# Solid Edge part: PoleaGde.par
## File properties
Author: there
Template: iso metric part.par
Last saved by: there
Revision: 3
Application: Solid Edge
Precisión: 0.990
Username: there
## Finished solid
Body 1: solid body, 8 faces, 8 edges, 0 vertices.
  Faces by surface: cylinder 4, plane 4
  Edges by curve: circle 8
Bounding box of the edges (mm): 32.000 x 13.000 x 32.000, from (-16, -10, -16) to (16, 3, 16).
Cylindrical faces by radius (mm): R3.2 x1, R12.5 x1, R16 x2
Planar faces by outward normal: +y 2, -y 2
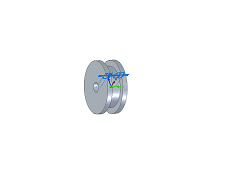
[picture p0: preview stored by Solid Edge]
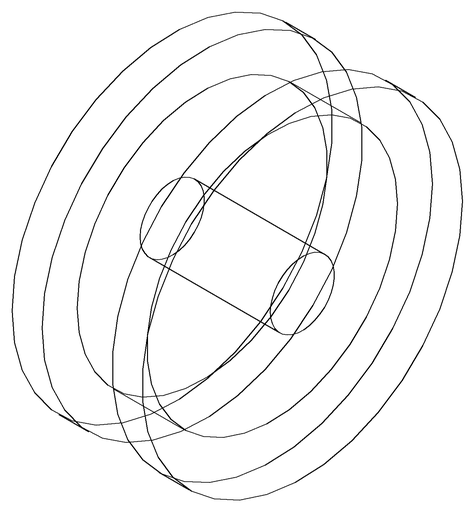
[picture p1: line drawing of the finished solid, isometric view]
